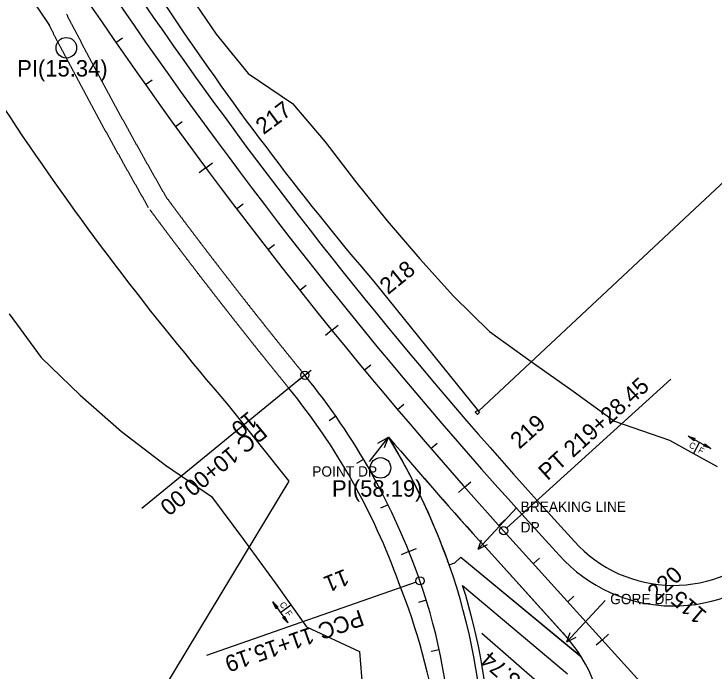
# Model space of a CAD drawing. Extents: x 2717836 to 2719883, y 337327 to 339806.
# Drawn here: x 2718764.3 to 2719104.8, y 338088.2 to 338408.2 of the extents above; entities that cross this region are included whole.
import ezdxf

# ---------------------------------------------------------------- set-up
doc = ezdxf.new("R2010")
doc.units = 0
for name, color, linetype in [('Level 1', 7, 'Continuous'), ('Level 2', 7, 'Continuous'), ('Level 22', 7, 'Continuous'), ('Level 23', 7, 'Continuous'), ('Level 3', 7, 'Continuous'), ('Level 31', 7, 'Continuous'), ('Level 52', 7, 'Continuous'), ('Level 6', 7, 'Continuous'), ('Level 60', 7, 'Continuous'), ('Level 61', 7, 'Continuous'), ('Level 62', 7, 'Continuous'), ('Level 8', 7, 'Continuous')]:
    doc.layers.add(name, color=color, linetype=linetype)

msp = doc.modelspace()

# ---------------------------------------------------------------- linework, layer by layer
at = {"layer": 'Level 1'}
msp.add_line((2719002.47, 338156.9), (2719189.33, 337950.54), dxfattribs=at)
for centre, radius, start, end in [((2715303.11, 341318.59), 5000, 318.95467, 328.67948), ((2720744.45, 339734.24), 2350, 206.79977, 222.16044), ((2718650.19, 338023.77), 330, 19.2398, 39.2398), ((2718697.4, 338040.25), 280, 343.9547, 19.2398)]:
    msp.add_arc(centre, radius, start, end, dxfattribs=at)
at = {"layer": 'Level 2'}
for centre, radius, start, end in [((2718692.92, 338040.11), 300.27, 344.2175, 19.5026), ((2718976.55, 338055.91), 75, 318.8661, 42.1604)]:
    msp.add_arc(centre, radius, start, end, dxfattribs=at)
at = {"layer": 'Level 22'}
for p, q in [((2718848.86, 338418.64), (2718862.69, 338398.35)), ((2718862.69, 338398.35), (2718878.13, 338379.22)), ((2718878.13, 338379.22), (2718899.73, 338364.7)), ((2718899.73, 338364.7), (2718915.62, 338346.08)), ((2718915.62, 338346.08), (2718930.49, 338326.7)), ((2718930.49, 338326.7), (2718945.81, 338307.67)), ((2718945.81, 338307.67), (2718961.78, 338289.18)), ((2718961.78, 338289.18), (2718978.1, 338271)), ((2718978.1, 338271), (2718995.61, 338253.86)), ((2718761.89, 338262.37), (2718777.48, 338241.23)), ((2718995.61, 338253.86), (2719015.92, 338239.2)), ((2718777.48, 338241.23), (2718796.55, 338222.77)), ((2719015.92, 338239.2), (2719036.37, 338224.82)), ((2718796.55, 338222.77), (2718816.65, 338205.23)), ((2719036.37, 338224.82), (2719056.38, 338210.21)), ((2719056.38, 338210.21), (2719083.16, 338200.89)), ((2718816.65, 338205.23), (2718837.98, 338188.83)), ((2719083.16, 338200.89), (2719094.77, 338194.54)), ((2719094.77, 338194.54), (2719106.38, 338188.19)), ((2718837.98, 338188.83), (2718860.37, 338173.48)), ((2718860.37, 338173.48), (2718875.97, 338152.58)), ((2718875.97, 338152.58), (2718891.4, 338131.5)), ((2718891.4, 338131.5), (2718898.97, 338120.79)), ((2718898.97, 338120.79), (2718906.54, 338110.09)), ((2718906.54, 338110.09), (2718932.31, 338098.2)), ((2718932.31, 338098.2), (2718934.9, 338066.65))]:
    msp.add_line(p, q, dxfattribs=at)
at = {"layer": 'Level 23'}
for p, q in [((2719374.17, 338574.5), (2718990.26, 338215.01)), ((2718939.3, 338278.13), (2718990.26, 338215.01)), ((2718868.5, 338217.98), (2718898.01, 338180.98)), ((2718898.01, 338180.98), (2718493, 337510.9))]:
    msp.add_line(p, q, dxfattribs=at)
msp.add_lwpolyline([(2718989.7, 338213.43), (2718988.66, 338214.51), (2718989.74, 338215.55), (2718990.78, 338214.47)], close=True, dxfattribs=at)
for centre, start, end in [((2720030.05, 339206.57), 206.96023, 220.40436), ((2719954.56, 339151.91), 206.65897, 220.69325)]:
    msp.add_arc(centre, 1432.39, start, end, dxfattribs=at)
at = {"layer": 'Level 3'}
for p, q in [((2719011.37, 338164.95), (2719029.47, 338144.96)), ((2718993.58, 338148.84), (2719031.25, 338107.23)), ((2718975.96, 338140.35), (2718978.77, 338141.36)), ((2718981.73, 338144.04), (2718978.77, 338141.36)), ((2718981.73, 338144.04), (2719039.16, 338096.51)), ((2719031.25, 338107.23), (2719032.14, 338106.25)), ((2719039.16, 338096.51), (2719040.11, 338095.72))]:
    msp.add_line(p, q, dxfattribs=at)
for centre, radius, start, end in [((2720744.45, 339734.24), 2338, 206.79977, 222.16044), ((2718650.19, 338023.77), 330, 19.2398, 39.2398), ((2718650.19, 338023.77), 330, 19.2398, 39.2398), ((2718662.07, 338029.42), 332.92, 19.8259, 31.3168), ((2720759.57, 339747.51), 2382.12, 220.43651, 222.14825), ((2721152.65, 340103.72), 2912.58, 222.15462, 222.1586), ((2719085.06, 338195.3), 75, 222.1604, 316.7247), ((2718640.38, 338021.68), 355.94, 19.4749, 19.8142), ((2718697.4, 338040.25), 280, 343.9547, 19.2398), ((2718697.4, 338040.25), 280, 343.9547, 19.2398)]:
    msp.add_arc(centre, radius, start, end, dxfattribs=at)
for points in [[(2718789.79, 338408.22), (2718790.1, 338407.61), (2718790.41, 338407.01), (2718790.73, 338406.4), (2718791.04, 338405.79), (2718791.36, 338405.18), (2718791.67, 338404.58), (2718791.99, 338403.97), (2718792.31, 338403.36), (2718792.62, 338402.76), (2718792.94, 338402.15), (2718793.25, 338401.54), (2718793.57, 338400.93), (2718793.88, 338400.33), (2718794.2, 338399.72), (2718794.52, 338399.11), (2718794.84, 338398.51), (2718795.16, 338397.9), (2718795.47, 338397.3), (2718795.79, 338396.69), (2718796.1, 338396.09), (2718796.43, 338395.48), (2718796.74, 338394.88), (2718797.06, 338394.27), (2718797.38, 338393.66), (2718797.7, 338393.06), (2718798.02, 338392.45), (2718798.33, 338391.85), (2718798.66, 338391.24), (2718798.97, 338390.64), (2718799.3, 338390.03), (2718799.62, 338389.42), (2718799.93, 338388.82), (2718800.26, 338388.21), (2718800.57, 338387.61), (2718800.9, 338387), (2718801.21, 338386.4), (2718801.54, 338385.79), (2718801.86, 338385.18), (2718802.18, 338384.58), (2718802.5, 338383.97), (2718802.82, 338383.37), (2718803.15, 338382.77), (2718803.47, 338382.17), (2718803.79, 338381.56), (2718804.12, 338380.95), (2718804.44, 338380.35), (2718804.76, 338379.74), (2718805.08, 338379.14), (2718805.41, 338378.54), (2718805.73, 338377.94), (2718806.05, 338377.33), (2718806.38, 338376.72), (2718806.7, 338376.12), (2718807.03, 338375.52), (2718807.35, 338374.92), (2718807.67, 338374.31), (2718808, 338373.71), (2718808.32, 338373.1), (2718808.64, 338372.51), (2718808.97, 338371.9), (2718809.3, 338371.29), (2718809.62, 338370.69), (2718809.95, 338370.09), (2718810.27, 338369.49), (2718810.6, 338368.88), (2718810.93, 338368.29), (2718811.26, 338367.68), (2718811.58, 338367.07), (2718811.91, 338366.48), (2718812.24, 338365.87), (2718812.56, 338365.27), (2718812.89, 338364.67), (2718813.22, 338364.07), (2718813.55, 338363.46)], [(2718813.55, 338363.46), (2718813.88, 338362.86), (2718814.2, 338362.26), (2718814.53, 338361.65), (2718814.86, 338361.06), (2718815.19, 338360.45), (2718815.52, 338359.85), (2718815.85, 338359.25), (2718816.18, 338358.64), (2718816.51, 338358.05), (2718816.84, 338357.44), (2718817.16, 338356.85), (2718817.5, 338356.24), (2718817.82, 338355.64), (2718818.16, 338355.04), (2718818.49, 338354.44), (2718818.82, 338353.84), (2718819.15, 338353.23), (2718819.48, 338352.64), (2718819.81, 338352.03), (2718820.14, 338351.44), (2718820.48, 338350.83), (2718820.81, 338350.24), (2718821.14, 338349.63), (2718821.48, 338349.03), (2718821.8, 338348.43), (2718822.14, 338347.83), (2718822.47, 338347.24), (2718822.8, 338346.63), (2718823.13, 338346.04), (2718823.47, 338345.43), (2718823.81, 338344.83), (2718824.14, 338344.23), (2718824.47, 338343.63), (2718824.81, 338343.04), (2718825.14, 338342.43), (2718825.47, 338341.84), (2718825.81, 338341.24), (2718826.15, 338340.63), (2718826.48, 338340.04), (2718826.82, 338339.44), (2718827.15, 338338.84), (2718827.49, 338338.24), (2718827.82, 338337.65), (2718828.16, 338337.04), (2718828.5, 338336.44), (2718828.83, 338335.85), (2718829.17, 338335.24), (2718829.5, 338334.65), (2718829.84, 338334.05), (2718830.18, 338333.45), (2718830.52, 338332.85), (2718830.86, 338332.25), (2718831.19, 338331.66), (2718831.53, 338331.06), (2718831.87, 338330.46), (2718832.21, 338329.86), (2718832.54, 338329.27), (2718832.89, 338328.67), (2718833.22, 338328.07), (2718833.56, 338327.47), (2718833.9, 338326.87), (2718834.24, 338326.28), (2718834.58, 338325.68), (2718834.92, 338325.09), (2718835.26, 338324.49), (2718835.6, 338323.89), (2718835.94, 338323.29), (2718836.28, 338322.69), (2718836.62, 338322.1), (2718836.97, 338321.5), (2718837.3, 338320.91), (2718837.65, 338320.31), (2718838.33, 338319.12)], [(2718838.33, 338319.12), (2718838.77, 338318.52), (2718839.22, 338317.92), (2718839.66, 338317.33), (2718840.1, 338316.73), (2718840.54, 338316.14), (2718840.99, 338315.54), (2718841.43, 338314.95), (2718841.87, 338314.36), (2718842.32, 338313.76), (2718842.76, 338313.17), (2718843.21, 338312.57), (2718843.65, 338311.98), (2718844.09, 338311.39), (2718844.54, 338310.79), (2718844.98, 338310.2), (2718845.43, 338309.6), (2718845.87, 338309.01), (2718846.32, 338308.42), (2718846.76, 338307.83), (2718847.21, 338307.24), (2718847.66, 338306.64), (2718848.1, 338306.05), (2718848.55, 338305.45), (2718848.99, 338304.86), (2718849.44, 338304.28), (2718849.89, 338303.68), (2718850.33, 338303.09), (2718850.78, 338302.49), (2718851.23, 338301.91), (2718851.68, 338301.31), (2718852.12, 338300.72), (2718852.57, 338300.13), (2718853.02, 338299.54), (2718853.47, 338298.95), (2718853.92, 338298.36), (2718854.37, 338297.77), (2718854.82, 338297.17), (2718855.26, 338296.59), (2718855.71, 338296), (2718856.16, 338295.4), (2718856.61, 338294.82), (2718857.06, 338294.22), (2718857.51, 338293.64), (2718857.96, 338293.05), (2718858.41, 338292.46), (2718858.86, 338291.87), (2718859.32, 338291.28), (2718859.76, 338290.69), (2718860.22, 338290.1), (2718860.67, 338289.51), (2718861.12, 338288.93), (2718861.57, 338288.34), (2718862.02, 338287.75), (2718862.48, 338287.16), (2718862.93, 338286.57), (2718863.38, 338285.99), (2718863.83, 338285.4), (2718864.28, 338284.81), (2718864.74, 338284.22), (2718865.19, 338283.64), (2718865.65, 338283.05), (2718866.1, 338282.46), (2718866.55, 338281.88), (2718867.01, 338281.29), (2718867.46, 338280.7), (2718867.91, 338280.11), (2718868.37, 338279.53), (2718868.82, 338278.95), (2718869.28, 338278.36), (2718869.73, 338277.77), (2718870.19, 338277.18), (2718870.64, 338276.6), (2718871.1, 338276.01), (2718871.55, 338275.43)], [(2718871.55, 338275.43), (2718872.01, 338274.85), (2718872.47, 338274.26), (2718872.92, 338273.68), (2718873.38, 338273.09), (2718873.83, 338272.51), (2718874.29, 338271.92), (2718874.75, 338271.34), (2718875.2, 338270.76), (2718875.66, 338270.17), (2718876.12, 338269.59), (2718876.58, 338269), (2718877.03, 338268.42), (2718877.49, 338267.84), (2718877.95, 338267.25), (2718878.41, 338266.67), (2718878.87, 338266.08), (2718879.33, 338265.5), (2718879.79, 338264.92), (2718880.25, 338264.34), (2718880.7, 338263.76), (2718881.17, 338263.17), (2718881.62, 338262.59), (2718882.09, 338262.01), (2718882.54, 338261.43), (2718883, 338260.85), (2718883.46, 338260.26), (2718883.92, 338259.69), (2718884.39, 338259.1), (2718884.85, 338258.52), (2718885.31, 338257.94), (2718885.77, 338257.36), (2718886.23, 338256.78), (2718886.69, 338256.2), (2718887.15, 338255.62), (2718887.62, 338255.04), (2718888.08, 338254.46), (2718888.54, 338253.88), (2718889, 338253.3), (2718889.46, 338252.72), (2718889.93, 338252.14), (2718890.39, 338251.56), (2718890.86, 338250.98), (2718891.32, 338250.4), (2718891.78, 338249.83), (2718892.25, 338249.24), (2718892.71, 338248.67), (2718893.18, 338248.08), (2718893.64, 338247.51), (2718894.11, 338246.93), (2718894.57, 338246.35), (2718895.03, 338245.78), (2718895.5, 338245.2), (2718895.96, 338244.62), (2718896.43, 338244.04), (2718896.89, 338243.46), (2718897.36, 338242.89), (2718897.83, 338242.31), (2718898.29, 338241.74), (2718898.76, 338241.15), (2718899.22, 338240.58), (2718899.7, 338240), (2718900.16, 338239.43), (2718900.62, 338238.85), (2718901.09, 338238.27), (2718901.56, 338237.7), (2718902.03, 338237.12), (2718902.5, 338236.55), (2718902.96, 338235.98), (2718903.43, 338235.4), (2718903.9, 338234.83), (2718904.37, 338234.25), (2718904.84, 338233.67), (2718905.78, 338232.52)]]:
    msp.add_spline(points, degree=3, dxfattribs=at)
at = {"layer": 'Level 31'}
for p, q in [((2718813.86, 338394.34), (2718817.15, 338396.62)), ((2718828.22, 338373.88), (2718831.49, 338376.2)), ((2718842.8, 338353.57), (2718846.04, 338355.92)), ((2718857.6, 338333.42), (2718860.81, 338335.81)), ((2718857.6, 338333.42), (2718854.39, 338331.04)), ((2718872.61, 338313.43), (2718875.79, 338315.85)), ((2718887.83, 338293.6), (2718890.99, 338296.05)), ((2718903.26, 338273.93), (2718906.39, 338276.41)), ((2718918.9, 338254.42), (2718922.01, 338256.94)), ((2718918.9, 338254.42), (2718915.79, 338251.9)), ((2718934.74, 338235.09), (2718937.82, 338237.64)), ((2718905.78, 338232.52), (2718908.88, 338235.05)), ((2718904.23, 338231.26), (2718826.46, 338167.74)), ((2718905.78, 338232.52), (2718902.68, 338229.99)), ((2719003.96, 338158.24), (2719083.85, 338230.58)), ((2718950.8, 338215.92), (2718953.85, 338218.5)), ((2718920.84, 338212.58), (2718917.56, 338210.29)), ((2718967.05, 338196.92), (2718970.07, 338199.54)), ((2718934.36, 338191.55), (2718930.91, 338189.52)), ((2718983.5, 338178.1), (2718986.5, 338180.75)), ((2718983.5, 338178.1), (2718980.51, 338175.45)), ((2718946.24, 338169.56), (2718942.65, 338167.8)), ((2719000.16, 338159.46), (2719003.13, 338162.14)), ((2718956.43, 338146.74), (2718960.14, 338148.23)), ((2718956.43, 338146.74), (2718952.71, 338145.25)), ((2719016.94, 338140.92), (2719019.9, 338143.61)), ((2718959.87, 338131.86), (2718857.93, 338096.28)), ((2719033.72, 338122.39), (2719036.68, 338125.08)), ((2718964.83, 338123.2), (2718961.01, 338122.02)), ((2719072.55, 338036.63), (2718991.88, 338106.86)), ((2719050.5, 338103.86), (2719047.53, 338101.18)), ((2719050.5, 338103.86), (2719053.46, 338106.55)), ((2718971.16, 338099.03), (2718967.25, 338098.19))]:
    msp.add_line(p, q, dxfattribs=at)
for centre, radius in [((2718789.76, 338391.81), 5), ((2718905.78, 338232.52), 2), ((2718942.59, 338187.46), 5), ((2719002.47, 338156.9), 2), ((2718961.76, 338132.52), 2)]:
    msp.add_circle(centre, radius, dxfattribs=at)
at = {"layer": 'Level 52'}
for p, q in [((2719092.24, 338202.95), (2719103.21, 338196.95)), ((2719097.73, 338199.95), (2719094.77, 338194.54)), ((2718890.26, 338122.28), (2718897.48, 338112.08)), ((2718893.87, 338117.18), (2718898.97, 338120.79))]:
    msp.add_line(p, q, dxfattribs=at)
for points in [[(2719092.24, 338202.95), (2719095.69, 338201.75), (2719094.61, 338201.65), (2719095.1, 338200.67)], [(2719103.21, 338196.95), (2719099.76, 338198.15), (2719100.84, 338198.25), (2719100.35, 338199.23)], [(2718890.26, 338122.28), (2718892.83, 338119.69), (2718891.81, 338120.08), (2718891.83, 338118.98)], [(2718897.48, 338112.08), (2718894.9, 338114.67), (2718895.92, 338114.29), (2718895.91, 338115.38)]]:
    msp.add_lwpolyline(points, close=True, dxfattribs=at)
at = {"layer": 'Level 6'}
for p, q in [((2719018.78, 338171.66), (2719036.88, 338151.67)), ((2718982.51, 338130.31), (2719033.5, 338087.25))]:
    msp.add_line(p, q, dxfattribs=at)
for centre, radius, start, end in [((2720744.45, 339734.24), 2372, 206.79977, 214.15238), ((2720744.45, 339734.24), 2328, 208.64257, 222.16044), ((2718650.19, 338023.77), 320, 19.6898, 39.2398), ((2719085.06, 338195.3), 65, 222.1604, 316.7247), ((2718654.26, 338013.03), 320, 8.6881, 21.747), ((2718697.4, 338040.25), 299, 346.4135, 17.5292)]:
    msp.add_arc(centre, radius, start, end, dxfattribs=at)
for points in [[(2718780.91, 338403.62), (2718781.22, 338403.02), (2718781.53, 338402.41), (2718781.85, 338401.8), (2718782.17, 338401.19), (2718782.48, 338400.58), (2718782.8, 338399.97), (2718783.12, 338399.35), (2718783.44, 338398.75), (2718783.75, 338398.14), (2718784.07, 338397.53), (2718784.38, 338396.92), (2718784.7, 338396.31), (2718785.02, 338395.71), (2718785.34, 338395.09), (2718785.66, 338394.48), (2718785.97, 338393.88), (2718786.29, 338393.26), (2718786.61, 338392.66), (2718786.93, 338392.05), (2718787.25, 338391.44), (2718787.57, 338390.83), (2718787.89, 338390.23), (2718788.21, 338389.61), (2718788.53, 338389), (2718788.85, 338388.4), (2718789.17, 338387.79), (2718789.49, 338387.18), (2718789.81, 338386.57), (2718790.13, 338385.97), (2718790.46, 338385.35), (2718790.78, 338384.75), (2718791.09, 338384.14), (2718791.42, 338383.53), (2718791.74, 338382.93), (2718792.06, 338382.32), (2718792.38, 338381.72), (2718792.71, 338381.1), (2718793.03, 338380.49), (2718793.35, 338379.89), (2718793.68, 338379.28), (2718794, 338378.68), (2718794.32, 338378.07), (2718794.64, 338377.46), (2718794.97, 338376.85), (2718795.29, 338376.24), (2718795.61, 338375.64), (2718795.94, 338375.03), (2718796.26, 338374.43), (2718796.59, 338373.82), (2718796.91, 338373.22), (2718797.24, 338372.6), (2718797.57, 338372), (2718797.89, 338371.4), (2718798.22, 338370.79), (2718798.54, 338370.18), (2718798.87, 338369.57), (2718799.19, 338368.97), (2718799.52, 338368.36), (2718799.84, 338367.76), (2718800.18, 338367.15), (2718800.5, 338366.54), (2718800.82, 338365.94), (2718801.15, 338365.33), (2718801.48, 338364.73), (2718801.81, 338364.12), (2718802.13, 338363.52), (2718802.47, 338362.91), (2718802.79, 338362.3), (2718803.12, 338361.71), (2718803.45, 338361.1), (2718803.78, 338360.5), (2718804.11, 338359.89), (2718804.43, 338359.29), (2718804.77, 338358.67)], [(2718804.77, 338358.67), (2718805.1, 338358.07), (2718805.42, 338357.47), (2718805.76, 338356.86), (2718806.08, 338356.26), (2718806.42, 338355.66), (2718806.74, 338355.06), (2718807.08, 338354.44), (2718807.41, 338353.84), (2718807.74, 338353.24), (2718808.07, 338352.63), (2718808.4, 338352.04), (2718808.73, 338351.43), (2718809.06, 338350.83), (2718809.4, 338350.21), (2718809.73, 338349.61), (2718810.06, 338349.02), (2718810.39, 338348.41), (2718810.72, 338347.81), (2718811.06, 338347.2), (2718811.39, 338346.6), (2718811.72, 338346), (2718812.05, 338345.4), (2718812.4, 338344.79), (2718812.73, 338344.19), (2718813.06, 338343.59), (2718813.39, 338342.98), (2718813.73, 338342.38), (2718814.06, 338341.78), (2718814.39, 338341.18), (2718814.73, 338340.57), (2718815.07, 338339.97), (2718815.4, 338339.37), (2718815.74, 338338.77), (2718816.07, 338338.17), (2718816.41, 338337.56), (2718816.74, 338336.96), (2718817.08, 338336.35), (2718817.42, 338335.75), (2718817.75, 338335.16), (2718818.09, 338334.55), (2718818.43, 338333.95), (2718818.77, 338333.35), (2718819.1, 338332.75), (2718819.44, 338332.14), (2718819.78, 338331.54), (2718820.12, 338330.95), (2718820.46, 338330.34), (2718820.79, 338329.74), (2718821.13, 338329.14), (2718821.47, 338328.54), (2718821.81, 338327.93), (2718822.15, 338327.34), (2718822.49, 338326.74), (2718822.83, 338326.14), (2718823.16, 338325.54), (2718823.51, 338324.94), (2718823.84, 338324.34), (2718824.19, 338323.74), (2718824.52, 338323.14), (2718824.87, 338322.53), (2718825.21, 338321.93), (2718825.55, 338321.34), (2718825.89, 338320.74), (2718826.23, 338320.14), (2718826.57, 338319.54), (2718826.91, 338318.94), (2718827.26, 338318.33), (2718827.6, 338317.74), (2718827.94, 338317.14), (2718828.28, 338316.54), (2718828.62, 338315.94), (2718828.97, 338315.34), (2718829.65, 338314.15)], [(2718830.3, 338313.15), (2718830.74, 338312.56), (2718831.19, 338311.96), (2718831.63, 338311.36), (2718832.08, 338310.76), (2718832.52, 338310.17), (2718832.97, 338309.57), (2718833.41, 338308.97), (2718833.86, 338308.38), (2718834.31, 338307.78), (2718834.75, 338307.18), (2718835.2, 338306.58), (2718835.64, 338305.99), (2718836.08, 338305.4), (2718836.54, 338304.79), (2718836.98, 338304.2), (2718837.43, 338303.6), (2718837.87, 338303.01), (2718838.33, 338302.41), (2718838.77, 338301.82), (2718839.21, 338301.23), (2718839.67, 338300.63), (2718840.11, 338300.03), (2718840.56, 338299.43), (2718841.01, 338298.84), (2718841.46, 338298.25), (2718841.91, 338297.65), (2718842.35, 338297.06), (2718842.81, 338296.46), (2718843.25, 338295.87), (2718843.71, 338295.27), (2718844.15, 338294.68), (2718844.6, 338294.09), (2718845.05, 338293.49), (2718845.5, 338292.91), (2718845.96, 338292.31), (2718846.4, 338291.72), (2718846.86, 338291.12), (2718847.31, 338290.53), (2718847.75, 338289.94), (2718848.21, 338289.34), (2718848.66, 338288.76), (2718849.11, 338288.16), (2718849.56, 338287.57), (2718850.01, 338286.98), (2718850.47, 338286.38), (2718850.92, 338285.8), (2718851.38, 338285.2), (2718851.83, 338284.61), (2718852.28, 338284.02), (2718852.73, 338283.43), (2718853.18, 338282.84), (2718853.64, 338282.24), (2718854.09, 338281.66), (2718854.55, 338281.06), (2718855, 338280.48), (2718855.45, 338279.89), (2718855.91, 338279.29), (2718856.36, 338278.71), (2718856.82, 338278.11), (2718857.27, 338277.53), (2718857.73, 338276.93), (2718858.19, 338276.35), (2718858.64, 338275.76), (2718859.1, 338275.17), (2718859.55, 338274.58), (2718860.01, 338273.99), (2718860.46, 338273.4), (2718860.92, 338272.82), (2718861.38, 338272.22), (2718861.83, 338271.64), (2718862.29, 338271.05), (2718862.75, 338270.46), (2718863.21, 338269.87), (2718863.66, 338269.29)], [(2718863.66, 338269.28), (2718864.12, 338268.7), (2718864.58, 338268.11), (2718865.04, 338267.53), (2718865.5, 338266.93), (2718865.95, 338266.35), (2718866.42, 338265.76), (2718866.87, 338265.17), (2718867.33, 338264.59), (2718867.79, 338264), (2718868.25, 338263.42), (2718868.71, 338262.83), (2718869.17, 338262.24), (2718869.63, 338261.66), (2718870.09, 338261.07), (2718870.55, 338260.49), (2718871.01, 338259.9), (2718871.47, 338259.32), (2718871.93, 338258.73), (2718872.39, 338258.15), (2718872.85, 338257.57), (2718873.32, 338256.98), (2718873.77, 338256.39), (2718874.24, 338255.8), (2718874.7, 338255.22), (2718875.16, 338254.64), (2718875.63, 338254.05), (2718876.09, 338253.48), (2718876.55, 338252.89), (2718877.01, 338252.31), (2718877.48, 338251.72), (2718877.94, 338251.14), (2718878.4, 338250.56), (2718878.87, 338249.97), (2718879.33, 338249.39), (2718879.8, 338248.8), (2718880.26, 338248.23), (2718880.72, 338247.65), (2718881.19, 338247.06), (2718881.65, 338246.48), (2718882.12, 338245.89), (2718882.58, 338245.32), (2718883.05, 338244.73), (2718883.51, 338244.15), (2718883.98, 338243.57), (2718884.44, 338242.99), (2718884.91, 338242.41), (2718885.38, 338241.82), (2718885.84, 338241.25), (2718886.31, 338240.66), (2718886.78, 338240.09), (2718887.24, 338239.51), (2718887.71, 338238.92), (2718888.18, 338238.35), (2718888.65, 338237.76), (2718889.11, 338237.18), (2718889.58, 338236.61), (2718890.05, 338236.03), (2718890.51, 338235.45), (2718890.99, 338234.86), (2718891.45, 338234.29), (2718891.93, 338233.71), (2718892.39, 338233.13), (2718892.86, 338232.56), (2718893.33, 338231.97), (2718893.8, 338231.4), (2718894.27, 338230.82), (2718894.74, 338230.24), (2718895.21, 338229.67), (2718895.68, 338229.08), (2718896.15, 338228.51), (2718896.62, 338227.93), (2718897.09, 338227.35), (2718898.03, 338226.2)]]:
    msp.add_spline(points, degree=3, dxfattribs=at)
at = {"layer": 'Level 60'}
for p, q in [((2719051.89, 338122.96), (2719033.23, 338102.85)), ((2719033.23, 338102.85), (2719034.86, 338107.38)), ((2719033.23, 338102.85), (2719037.76, 338105.2))]:
    msp.add_line(p, q, dxfattribs=at)
at = {"layer": 'Level 61'}
for p, q in [((2719008.7, 338167.99), (2718990.04, 338147.88)), ((2718990.04, 338147.88), (2718991.67, 338152.41)), ((2718990.04, 338147.88), (2718994.57, 338150.23))]:
    msp.add_line(p, q, dxfattribs=at)
at = {"layer": 'Level 62'}
for p in [(2718937.16, 338190.61), (2718941.32, 338199.49), (2718944.58, 338197.32)]:
    msp.add_line(p, (2718946.48, 338202.46), dxfattribs=at)
at = {"layer": 'Level 8'}
for p, q in [((2718993.58, 338148.84), (2719032.14, 338106.25)), ((2718975.96, 338140.35), (2718978.77, 338141.36)), ((2718981.73, 338144.04), (2718978.77, 338141.36)), ((2718981.73, 338144.04), (2719040.05, 338095.77))]:
    msp.add_line(p, q, dxfattribs=at)
for centre, radius, start, end in [((2720744.45, 339734.24), 2362, 220.42917, 222.16044), ((2718650.19, 338023.78), 346, 19.6893, 31.0937), ((2718976.55, 338055.91), 75, 32.502, 42.1604)]:
    msp.add_arc(centre, radius, start, end, dxfattribs=at)

# ---------------------------------------------------------------- texts
at = {"layer": 'Level 31'}
for s, p in [('PI(15.34)', (2718765.85, 338377.81)), ('PI(58.19)', (2718919, 338173.46))]:
    msp.add_text(s, height=8, dxfattribs=at).set_placement(p)
for s, rotation, p in [('217', 36.5905, (2718885.68, 338349.29)), ('218', 39.0286, (2718946.28, 338271.47)), ('PT 219+28.45', 42.1604, (2719023.84, 338180.97)), ('10', 219.2398, (2718878.46, 338215.38)), ('219', 41.4667, (2719010.13, 338196.29)), ('PC 10+00.00', 219.2398, (2718883.21, 338209.57)), ('11', 201.8775, (2718925.24, 338138.53)), ('220', 42.1604, (2719076.9, 338122.37)), ('115', 139.8286, (2719101.83, 338116.91)), ('PCC 11+15.19', 199.2398, (2718932.7, 338118.67)), ('PC 114+23.74', 138.9547, (2719047.63, 338053.69))]:
    msp.add_text(s, height=8, rotation=rotation, dxfattribs=at).set_placement(p)
at = {"layer": 'Level 52'}
for s, rotation, p in [('C', 331.3352, (2719092.28, 338197.66)), ('F', 331.3352, (2719096.77, 338195.13)), ('C', 305.2872, (2718893.28, 338121.02)), ('F', 305.2872, (2718896.09, 338116.85))]:
    msp.add_text(s, height=3, rotation=rotation, dxfattribs=at).set_placement(p)
at = {"layer": 'Level 60'}
msp.add_text('GORE DP', height=5, dxfattribs=at).set_placement((2719054.28, 338121.17))
at = {"layer": 'Level 61'}
for s, p in [('BREAKING LINE ', (2719010.72, 338166.08)), ('DP', (2719010.72, 338156.08))]:
    msp.add_text(s, height=5, dxfattribs=at).set_placement(p)
at = {"layer": 'Level 62'}
msp.add_text('POINT DP', height=5, dxfattribs=at).set_placement((2718909.37, 338183.23))

doc.saveas('drawing.dxf')
